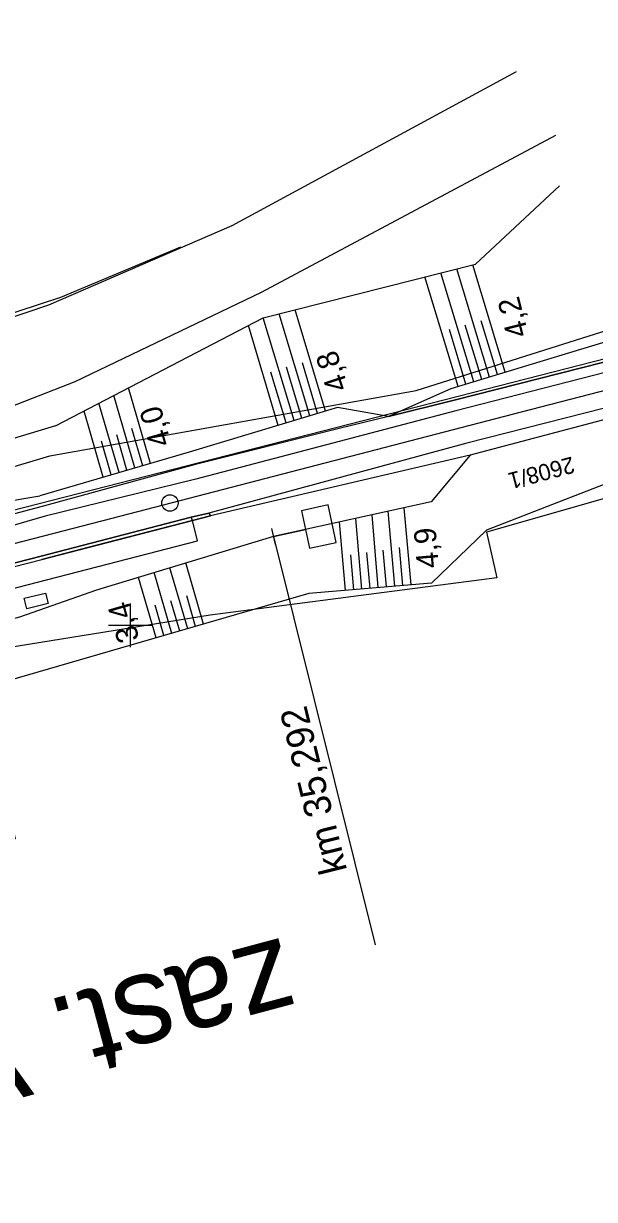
# Model space of a CAD drawing. Extents: x -806456 to -805395, y -1150847 to -1150506.
# Drawn here: x -806109.7 to -806057.6, y -1150752.4 to -1150645.1 of the extents above; entities that cross this region are included whole.
import ezdxf

# ---------------------------------------------------------------- set-up
doc = ezdxf.new("R2010")
doc.units = 0
for name, color, linetype in [('0381KM032-037P - Vrstva 1', 7, 'Continuous'), ('0381KM032-037P - Vrstva 14', 7, 'Continuous'), ('0381KM032-037P - Vrstva 17', 7, 'Continuous'), ('0381KM032-037P - Vrstva 23', 7, 'Continuous'), ('0381KM032-037P - Vrstva 25', 7, 'Continuous'), ('0381KM032-037P - Vrstva 4', 7, 'Continuous'), ('0381KM032-037P - Vrstva 48', 7, 'Continuous'), ('0381KM032-037P - Vrstva 49', 7, 'Continuous'), ('0381KM032-037P - Vrstva 51', 7, 'Continuous'), ('0381KM032-037P - Vrstva 57', 7, 'Continuous'), ('0381KM032-037P - Vrstva 7', 7, 'Continuous'), ('hran DP - hran DP', 7, 'Continuous'), ('krizky_1000 - Vrstva 1', 7, 'Continuous'), ('vyt_sit - polygon', 7, 'Continuous')]:
    doc.layers.add(name, color=color, linetype=linetype)

msp = doc.modelspace()

# ---------------------------------------------------------------- linework, layer by layer
at = {"layer": '0381KM032-037P - Vrstva 1'}
msp.add_lwpolyline([(-805989.76, -1150661.17), (-806027.03, -1150670.9), (-806064.32, -1150680.56), (-806101.67, -1150690.24), (-806138.44, -1150699.75), (-806158.28, -1150704.94), (-806163.64, -1150706.34), (-806175.38, -1150709.4), (-806186.46, -1150712.29), (-806205.2, -1150717.19), (-806213.26, -1150719.29)], dxfattribs=at)
at = {"layer": '0381KM032-037P - Vrstva 14'}
for p, q in [((-806094.31, -1150690.42), (-806094.43, -1150690.13)), ((-806093.88, -1150692.3), (-806094.31, -1150690.42)), ((-806092.84, -1150689.77), (-806092.67, -1150690)), ((-806161.45, -1150709.69), (-806093.88, -1150692.3))]:
    msp.add_line(p, q, dxfattribs=at)
for points in [[(-806154.89, -1150705.76), (-806154.2, -1150705.57), (-806132.57, -1150699.95), (-806108.13, -1150693.69), (-806094.43, -1150690.13), (-806092.84, -1150689.77), (-806094.43, -1150690.13), (-806108.12, -1150693.69), (-806132.57, -1150699.95), (-806154.2, -1150705.57), (-806154.88, -1150705.76)], [(-806154.82, -1150706.03), (-806154.13, -1150705.84), (-806132.47, -1150700.24), (-806108.06, -1150693.98), (-806094.31, -1150690.42), (-806092.67, -1150690)], [(-806092.67, -1150690), (-806094.31, -1150690.42), (-806103.16, -1150692.72), (-806108.06, -1150693.98)]]:
    msp.add_lwpolyline(points, dxfattribs=at)
at = {"layer": '0381KM032-037P - Vrstva 17'}
msp.add_lwpolyline([(-806169.28, -1150696.91), (-806165.68, -1150693.97), (-806155.41, -1150686.94), (-806141.03, -1150680.9), (-806121.85, -1150675.14), (-806106.33, -1150670.05), (-806095.39, -1150665.45)], dxfattribs=at)
at = {"layer": '0381KM032-037P - Vrstva 25'}
msp.add_lwpolyline([(-806109.45, -1150698.49), (-806109.68, -1150697.52), (-806107.74, -1150697.05), (-806107.5, -1150698.02), (-806109.45, -1150698.49)], dxfattribs=at)
at = {"layer": '0381KM032-037P - Vrstva 4'}
msp.add_line((-806068.97, -1150684.48), (-806092.67, -1150690), dxfattribs=at)
for points in [[(-805920.59, -1150645.08), (-805938.49, -1150646.69), (-805957, -1150650.24), (-805973.18, -1150654.13), (-805996.94, -1150660.52), (-806010.57, -1150664.04), (-806045.29, -1150673.07), (-806070.44, -1150679.45), (-806076.44, -1150680.94), (-806080.95, -1150682.04), (-806094.16, -1150685.34), (-806107.83, -1150689.09)], [(-805923.83, -1150646.61), (-805939.39, -1150648.49), (-805956.78, -1150651.56), (-805972.77, -1150655.27), (-805996.74, -1150661.47), (-806010.38, -1150665.11), (-806045.15, -1150673.98), (-806070.28, -1150680.43), (-806094.02, -1150686.67), (-806107.78, -1150690.05)], [(-805923.37, -1150650.9), (-805938.15, -1150652.42), (-805956.35, -1150655.74), (-805972.37, -1150659.35), (-805995.12, -1150665.03), (-806009.04, -1150668.86), (-806027.1, -1150673.31), (-806034.62, -1150675.7), (-806043.91, -1150677.85), (-806068.97, -1150684.48)], [(-805995.68, -1150664.21), (-806009.49, -1150668.04), (-806044.17, -1150677), (-806069.3, -1150683.37)], [(-806069.3, -1150683.37), (-806092.84, -1150689.77), (-806092.67, -1150690)], [(-806107.83, -1150689.09), (-806118.69, -1150691.97), (-806137.28, -1150697.2), (-806151.73, -1150700.28), (-806152.97, -1150701.48)], [(-806107.78, -1150690.05), (-806118.34, -1150693.12), (-806137.19, -1150697.81), (-806152.97, -1150701.48)]]:
    msp.add_lwpolyline(points, dxfattribs=at)
at = {"layer": '0381KM032-037P - Vrstva 48'}
for p, q in [((-806068.65, -1150677.78), (-806071.66, -1150667.84)), ((-806067.21, -1150677.34), (-806070.2, -1150667.47)), ((-806065.78, -1150676.91), (-806068.75, -1150667.1)), ((-806070.08, -1150678.21), (-806073.11, -1150668.21)), ((-806082.18, -1150680.45), (-806084.96, -1150671.2)), ((-806085.05, -1150681.32), (-806087.87, -1150671.94)), ((-806083.61, -1150680.89), (-806086.41, -1150671.57)), ((-806066.49, -1150677.12), (-806067.98, -1150672.21)), ((-806086.49, -1150681.75), (-806089.22, -1150672.65)), ((-806069.37, -1150678), (-806070.88, -1150673.01)), ((-806067.93, -1150677.56), (-806069.43, -1150672.61)), ((-806084.33, -1150681.1), (-806085.74, -1150676.43)), ((-806082.9, -1150680.67), (-806084.29, -1150676.03)), ((-806085.77, -1150681.53), (-806087.16, -1150676.91)), ((-806098.14, -1150685.22), (-806100.15, -1150678.32)), ((-806101.02, -1150686.06), (-806102.86, -1150679.73)), ((-806099.58, -1150685.64), (-806101.51, -1150679.03)), ((-806102.46, -1150686.48), (-806104.22, -1150680.44)), ((-806100.3, -1150685.85), (-806101.24, -1150682.61)), ((-806098.86, -1150685.43), (-806099.85, -1150682.05)), ((-806101.74, -1150686.27), (-806102.64, -1150683.18)), ((-806074.38, -1150696.3), (-806074.99, -1150689.27)), ((-806078.86, -1150696.69), (-806079.42, -1150690.24)), ((-806077.37, -1150696.56), (-806077.94, -1150689.92)), ((-806075.87, -1150696.43), (-806076.46, -1150689.59)), ((-806080.35, -1150696.82), (-806080.9, -1150690.56)), ((-806079.61, -1150696.76), (-806079.88, -1150693.58)), ((-806078.11, -1150696.63), (-806078.4, -1150693.35)), ((-806076.62, -1150696.5), (-806076.91, -1150693.13)), ((-806075.12, -1150696.37), (-806075.43, -1150692.9)), ((-806094.76, -1150700.32), (-806096.38, -1150694.75)), ((-806093.32, -1150699.9), (-806094.94, -1150694.31)), ((-806097.65, -1150701.15), (-806099.25, -1150695.62)), ((-806096.21, -1150700.74), (-806097.81, -1150695.18)), ((-806095.48, -1150700.53), (-806096.29, -1150697.75)), ((-806094.04, -1150700.11), (-806094.85, -1150697.32)), ((-806096.93, -1150700.94), (-806097.73, -1150698.17))]:
    msp.add_line(p, q, dxfattribs=at)
at = {"layer": '0381KM032-037P - Vrstva 49'}
for points in [[(-806076.44, -1150680.94), (-806070.44, -1150679.45), (-806045.29, -1150673.07), (-806010.57, -1150664.04), (-805996.94, -1150660.52), (-805973.18, -1150654.13), (-805957, -1150650.24), (-805938.49, -1150646.69)], [(-806106.83, -1150681.79), (-806087.86, -1150671.94), (-806068.49, -1150667.04), (-806060.84, -1150659.9)], [(-805995.12, -1150665.03), (-806009.04, -1150668.86), (-806027.1, -1150673.31), (-806034.62, -1150675.7), (-806043.91, -1150677.85), (-806068.97, -1150684.48)], [(-806046.76, -1150671.15), (-806070.76, -1150678.42)], [(-806070.76, -1150678.42), (-806076.44, -1150680.94), (-806081.09, -1150680.13), (-806094.64, -1150684.2), (-806108.26, -1150688.17)], [(-806042.38, -1150685.77), (-806037.14, -1150679.5), (-806067.5, -1150691.31), (-806072.52, -1150696.14), (-806083.69, -1150697.11)], [(-806106.83, -1150681.79), (-806120.86, -1150686.01), (-806130.84, -1150689.2), (-806140.72, -1150692.22), (-806149.98, -1150695.47), (-806155.41, -1150698.65)], [(-806068.97, -1150684.48), (-806072.55, -1150688.73), (-806086.94, -1150691.89)], [(-806155.86, -1150700.93), (-806155.37, -1150700.64), (-806154.96, -1150699.45), (-806154.58, -1150699.23), (-806153.89, -1150698.71), (-806149.38, -1150697.67), (-806139.49, -1150695.22), (-806130.93, -1150692.92), (-806118.59, -1150689.92), (-806108.26, -1150688.17)], [(-806086.94, -1150691.89), (-806103.09, -1150696.78), (-806110.1, -1150699.27), (-806113.94, -1150700.3), (-806116.98, -1150701.29), (-806117.57, -1150702.15), (-806117.47, -1150702.7), (-806118.52, -1150712.15), (-806144.33, -1150720.15), (-806155.42, -1150722.6), (-806156.37, -1150719.96), (-806156.92, -1150718.66), (-806157.56, -1150717.45), (-806160.48, -1150717.28), (-806160.29, -1150717.98), (-806160.2, -1150718.76), (-806166.07, -1150720.05), (-806166.41, -1150718.42)], [(-806083.69, -1150697.11), (-806113.19, -1150705.65), (-806111.06, -1150717.22), (-806110.51, -1150719.49), (-806126.08, -1150722.72), (-806134.13, -1150725.52)]]:
    msp.add_lwpolyline(points, dxfattribs=at)
at = {"layer": '0381KM032-037P - Vrstva 51'}
for points in [[(-806140.16, -1150681.15), (-806120.15, -1150675.05), (-806107.44, -1150670.76), (-806090.7, -1150663.5), (-806064.75, -1150649.45)], [(-806121.48, -1150684.16), (-806105.03, -1150677.76), (-806088.01, -1150669.6), (-806061.17, -1150655.26)]]:
    msp.add_lwpolyline(points, dxfattribs=at)
at = {"layer": '0381KM032-037P - Vrstva 7'}
for p, q in [((-806087.1, -1150691.15), (-806086.78, -1150692.62)), ((-806086.94, -1150691.89), (-806077.64, -1150729.17))]:
    msp.add_line(p, q, dxfattribs=at)
msp.add_lwpolyline([(-806086.94, -1150691.89), (-806084.01, -1150691.25), (-806083.64, -1150692.96), (-806081.2, -1150692.43), (-806081.94, -1150689.01), (-806084.38, -1150689.54), (-806084.01, -1150691.25)], dxfattribs=at)
msp.add_circle((-806096.38, -1150688.84), 0.75, dxfattribs=at)
at = {"layer": 'hran DP - hran DP'}
for p, q in [((-806073.91, -1150678.57), (-806039.45, -1150667.69)), ((-806107.35, -1150684.54), (-806073.91, -1150678.57)), ((-806152.11, -1150697.83), (-806107.35, -1150684.54)), ((-806051.33, -1150686.88), (-806067.49, -1150691.49)), ((-806067.49, -1150691.49), (-806066.55, -1150695.68)), ((-806066.55, -1150695.68), (-806092.7, -1150699.08)), ((-806092.7, -1150699.08), (-806114.99, -1150702.66))]:
    msp.add_line(p, q, dxfattribs=at)
at = {"layer": 'krizky_1000 - Vrstva 1'}
for points in [[(-806100, -1150698), (-806100, -1150702)], [(-806102, -1150700), (-806098, -1150700)]]:
    msp.add_lwpolyline(points, dxfattribs=at)
at = {"layer": 'vyt_sit - polygon'}
msp.add_line((-806134.24, -1150695.52), (-806002.92, -1150661.86), dxfattribs=at)

# ---------------------------------------------------------------- texts
at = {"layer": '0381KM032-037P - Vrstva 23'}
msp.add_text('zast. Vimperk', height=8, rotation=195, dxfattribs=at).set_placement((-806086.07, -1150728.44))
at = {"layer": '0381KM032-037P - Vrstva 48'}
for s, rotation, p in [('4,2', 104.1997, (-806063.65, -1150673.47)), ('4,8', 108.036, (-806080.07, -1150678.31)), ('4,0', 106.2287, (-806096.24, -1150683.39)), ('4,9', 94.9542, (-806071.83, -1150694.71)), ('3,4', 106.1463, (-806099.15, -1150701.26))]:
    msp.add_text(s, height=2, rotation=rotation, dxfattribs=at).set_placement(p)
at = {"layer": '0381KM032-037P - Vrstva 57'}
msp.add_text('2608/1', height=1.5, rotation=194.7572, dxfattribs=at).set_placement((-806059.69, -1150684.58))
at = {"layer": '0381KM032-037P - Vrstva 7'}
msp.add_text('km 35,292', height=2.5, rotation=103.9101, dxfattribs=at).set_placement((-806080.2, -1150722.36))

doc.saveas('drawing.dxf')
